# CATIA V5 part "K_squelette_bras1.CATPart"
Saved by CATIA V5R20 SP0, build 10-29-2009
Part number: squelette_bras1
Publications: "Point_origine", "Point_centre_liaison_pivot12", "Plan.1", "Droite.1", "axe_pivot12"
Bounding box of the stored display mesh (mm): x 0 to 0, y 0 to 0, z 0 to 170
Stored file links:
  G:\Khaled_CFAO_2011\SIL\SIL_GR2\pfradet\pfradet\Khaled\CAD_ThinkMOTION\K_squelette_bras1.CATPart
  G:\Khaled_CFAO_2011\SIL\SIL_GR2\pfradet\pfradet\Khaled\CAD_ThinkMOTION\K_squelette.CATProduct
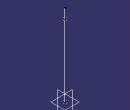
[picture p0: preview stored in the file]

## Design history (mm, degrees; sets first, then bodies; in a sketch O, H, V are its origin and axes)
Set1
  Point1 "Point_origine": linked copy from another document
  Point2 "Point_centre_liaison_pivot12": linked copy from another document
  Plane1: linked copy from another document
Set2
  Line1: type PtPt, FirstPoint Point1, SecondPoint Point2
  Line2 "axe_pivot12": type Normal, RefPoint Point2, RefSkin Plane1, Start 0, End 20
Body1 (main body)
